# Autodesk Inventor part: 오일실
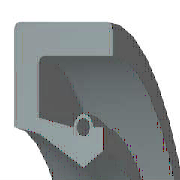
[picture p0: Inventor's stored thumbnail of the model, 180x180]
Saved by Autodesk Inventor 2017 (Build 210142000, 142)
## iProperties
IsCustomPart: 1
Created: 2015-12
Part Number: 오일실
Material: 고무
Description: 오일-실
Document SubType Name: Modeling
Standard: KS B 2804
Designer: mdu
Standards Organization: KS
Language: ko-KR
Size Designation: S - 15 30 7
Categories: <MemberInstance><Categories><Category DisplayName="샤프트 부품" InternalName="7f7aeb1f-a693-4053-b835-cee3144e0d98" Mnemonic="SHFT"><Category DisplayName="실링" Intern
Density: 0.93 g/cm^3
Appearance: 고무 - 검은색 - 버전 1.1
Mass: 1.64364 g
Surface Area: 26.6454 cm^2
Volume: 1.76736 cm^3
Author: mdu
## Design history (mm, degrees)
revolve "본체" stored, may be unused: angle "d17" = 90 deg
revolve "스프링1" stored, may be unused: angle "d18" = 90 deg
body "Solid1"
sketch "스케치1"
  geometry: L1 (0, 15)-(7, 15); L2 (7, 15)-(7, 13.75); L3 (7, 13.75)-(1.75, 13.75); L4 (0, 15)-(0, 9.6); L5 (0, 9.6)-(1.75, 9.25); L6 (1.75, 9.25)-(4.9, 7.5); L7 (4.9, 7.5)-(0, 7.5); L8 (6.3, 8.375)-(6.3, 9.6); L9 (0, 0)-(9.586, 0) reference; L10 (4.9, 7.5)-(6.3, 8.375); L11 (0, 18)-(0, -3) reference; L12 (-1.917, 0)-(11.503, 0) reference; L13 (4.2, 9.6)-(1.75, 10.09); L14 (1.75, 10.09)-(1.75, 13.75); L15 (6.3, 9.6)-(5.6, 9.6); C1 r 0.455 at (4.9, 9.6); A1 r 0.7 centre (4.9, 9.6) between (5.6, 9.6) and (4.2, 9.6)
  constraints: 26 end point, 5 horizontal alignment, 4 perpendicular, 2 centre point, 2 collinear, 2 horizontal, 2 parallel, 2 point on circle, 2 point on line, 2 vertical alignment, 1 coincident
  dimensions: "d0" = 30 diameter of L1 L9 (= SD2); "d1" = 16.75 diameter of L8.start L9 (= ABDM); "d2" = 1.25 distance of L1.end L2.end (computed from SD); "d3" = 0.91 diameter of C1 (= SPDI); "d4" = 1.4 diameter of A1 (= SPDA); "d5" = 15 diameter of L6.end L9 (= NND); "d6" = 18.5 diameter of L5.end L9 (= TKDM); "d7" = 19.2 diameter of L4.end L9 (= HLDM); "d8" = 4.9 distance from line of C1.centre L4 (= SPDST); "d9" = 6.3 distance between parallel lines of L8 L4 (= SDI); "d10" = 7 distance between parallel lines of L2 L4 (= SWDT); "d12" = 1.75 distance between parallel lines of L14 L4 (= SD)
fillet "모깎기1" dims "d11" = 0.3 (= RR)
other parameters: "SD2" = 30 [user parameter; used in 1 equation term], "SWDT" = 7 [user parameter; used in 1 equation term], "RR" = 0.3 [user parameter; used in 1 equation term], "SD" = 1.75 [user parameter; used in 2 equation terms], "NND" = 15 [user parameter; used in 1 equation term], "SPDA" = 1.4 [user parameter; used in 1 equation term], "SPDI" = 0.91 [user parameter; used in 1 equation term], "TKDM" = 18.5 [user parameter; used in 1 equation term], "HLDM" = 19.2 [user parameter; used in 1 equation term], "ABDM" = 16.75 [user parameter; used in 1 equation term], "SDI" = 6.3 [user parameter; used in 1 equation term], "SPDST" = 4.9 [user parameter; used in 1 equation term], "d13" = 0, "d14" = 0, "d15" = 0, "LAB" = 0.35 [user parameter]
